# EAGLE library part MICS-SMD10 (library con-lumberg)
CONNECTOR
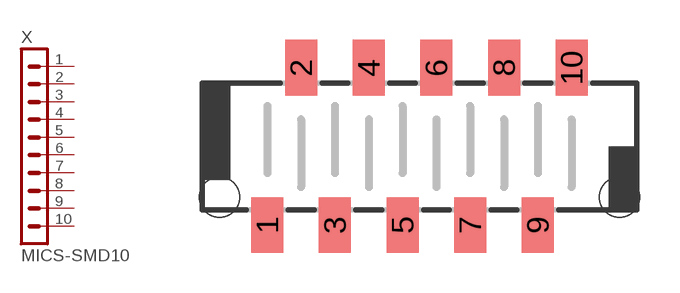
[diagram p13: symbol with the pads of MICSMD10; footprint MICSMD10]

Designator prefix X

## MICS-SMD10 (OC_FARNELL: unknown; OC_NEWARK: unknown)  [MICSMD10]
1  1  pas
2  2  pas
3  3  pas
4  4  pas
5  5  pas
6  6  pas
7  7  pas
8  8  pas
9  9  pas
10  10  pas

## Footprint MICSMD10 (pad centres in mm)
CONNECTOR
smd 1.2 x 2.1: 1 -5.715,-2.959; 2 -4.445,2.959; 3 -3.175,-2.959; 4 -1.905,2.959; 5 -0.635,-2.959; 6 0.635,2.959; 7 1.905,-2.959; 8 3.175,2.959; 9 4.445,-2.959; 10 5.715,2.959
hole 1.5 at 7.515,-1.912
hole 1.5 at -7.515,-1.912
